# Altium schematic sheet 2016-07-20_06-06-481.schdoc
size 193 x 143 mm; SheetNumber: 1; SheetTotal: 1
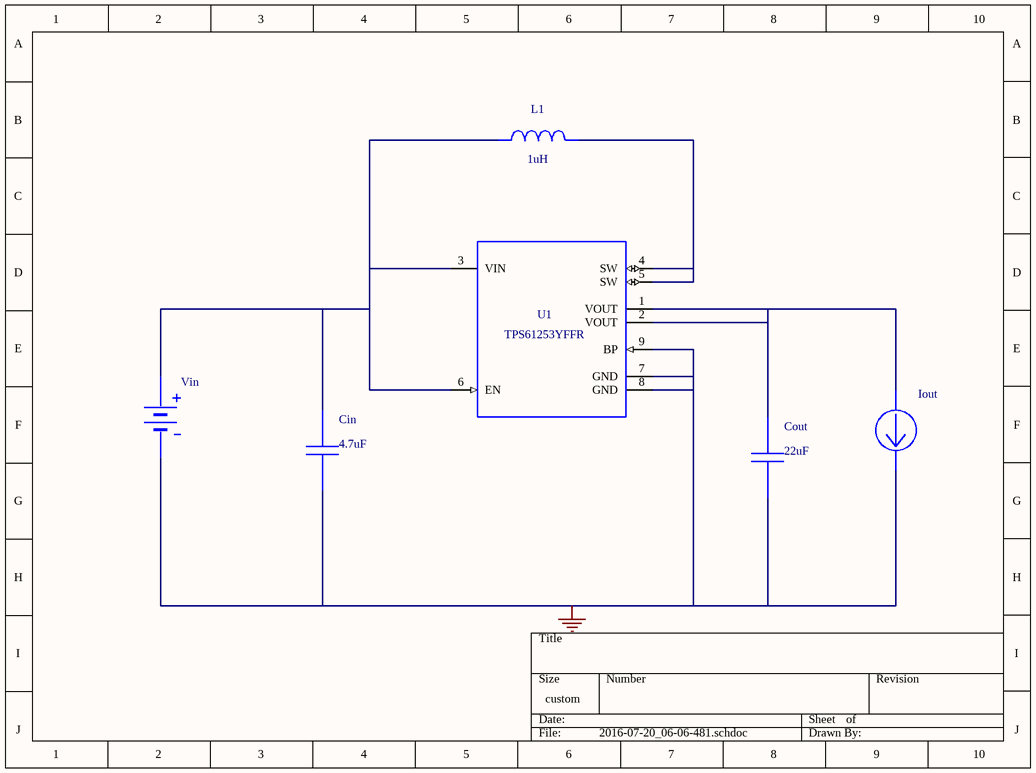
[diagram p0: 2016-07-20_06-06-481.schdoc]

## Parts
Cin  value 4.7uF  (hidden comment: GRM21BR61A475KA73L)
Cout  value 22uF  (hidden comment: LMK212BJ226MG-T)
Iout  WB_CURRENT_LOAD  (value not drawn)
L1  value 1uH  (hidden comment: XFL4020-102MEB)
U1  TPS61253YFFR
Vin  WB_BATTERY  (value not drawn)

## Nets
0: Cin.2 Cout.2 Iout.2(-) U1.7(GND) U1.8(GND) U1.9(BP) Vin.2(-)
NetCin_1: Cin.1 L1.1 U1.3(VIN) U1.6(EN) Vin.1(+)
NetCout_1: Cout.1 Iout.1(+) U1.1(VOUT) U1.2(VOUT)
NetL1_2: L1.2 U1.4(SW) U1.5(SW)

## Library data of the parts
Cin = GRM21BR61A475KA73L: GRM21BR61A475KA7; Manufacturer Name: MuRata
Cout = LMK212BJ226MG-T: Manufacturer Name: Taiyo Yuden
L1 = XFL4020-102MEB: Manufacturer Name: Coilcraft
U1 = TPS61253YFFR: Manufacturer Name: Texas Instruments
